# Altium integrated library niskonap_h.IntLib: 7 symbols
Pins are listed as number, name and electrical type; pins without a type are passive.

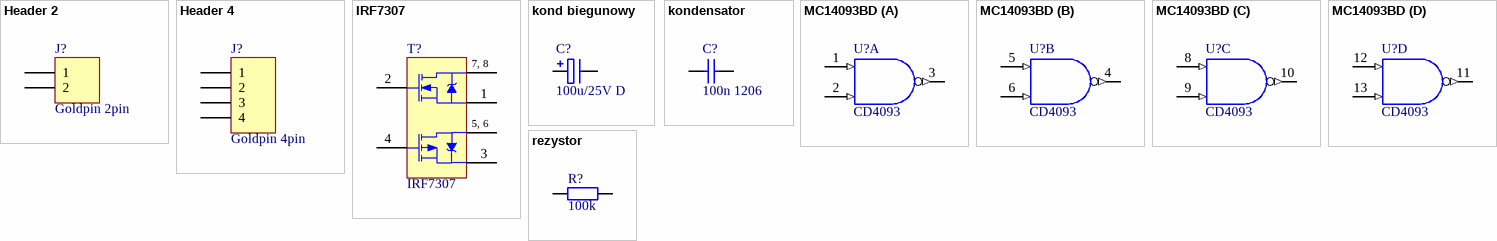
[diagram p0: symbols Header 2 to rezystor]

## Header 2
designator J?, comment Goldpin 2pin
Header, 2-Pin
footprint HDR1X2 (Connector; Header; 2 Position)
signal-integrity model Connector
pins: 1, 2

## Header 4
designator J?, comment Goldpin 4pin
Header, 4-Pin
footprint HDR1X4 (Connector; Header; 4 Position)
signal-integrity model Connector
pins: 1, 2, 3, 4

## IRF7307
designator T?
HEXFET Power MOSFET
footprint SO-8_N (SOIC, 8-Leads, Body 4.9x3.9mm, Pitch 1.27mm, IPC Medium Density)
footprint SO-8_L (SOIC, 8-Leads, Body 4.9x3.9mm, Pitch 1.27mm, IPC High Density)
footprint SO-8_M (SOIC, 8-Leads, Body 4.9x3.9mm, Pitch 1.27mm, IPC Low Density)
3D model SO-8 (8-Pin Plastic Small Outline Integrated Circuit 1.27 mm Pitch)
simulation model IRF7307 (SUBCKT)
pins: 1 S1, 2 G1, 3 S2, 4 G2, 5 D2, 6 D2, 7 D1, 8 D1

## kond biegunowy
designator C?, comment 100u/25V D
Polarized Capacitor
footprint Tantal B 3528-1411 (Capacitor, SM Tantalum; Body 3.5 x 2.8 mm (LxW typ))
footprint Tantal C 6032-2412 (Capacitor, SM Tantalum; Body 6.0 x 3.2 mm (LxW typ))
footprint Tantal D 7343-2917 (Capacitor, SM Tantalum; Body 7.3 x 4.3 mm (LxW typ))
footprint 2,5/5mm elektrolit
footprint 3,5/7mm elektrolit
footprint 5/10mm elektrolit
footprint 2,5/7mm elektrolit
footprint 7,5/16mm elektrolit
footprint 5/12,5mm elektrolit
footprint Tantal A 3216-1206 (Capacitor, SM Tantalum; Body 3.2 x 1.6 mm (LxW typ))
footprint A SMD elektrolit
footprint B SMD elektrolit
footprint C SMD elektrolit
footprint D SMD elektrolit
footprint E SMD elektrolit
footprint F SMD elektrolit
pins: 1, 2
1 alternate drawing of the same symbol

## kondensator
designator C?, comment 100n 1206
footprint kond 2,5mm
footprint kond 7,5mm
footprint kond 10mm
footprint MELF-0805 (Metal Electrode Face (MELF) Resistor; Body 2 x 1.4 mm (LxDia))
footprint MELF-1206 (Metal Electrode Face (MELF) Resistor; Body 3.2 x 1.8 mm (LxDia))
footprint kond 15mm
footprint kond 5mm chudy
footprint kond 5mm gruby
footprint kond 5mm sredni
footprint kond 5mm
pins: 1, 2

## MC14093BD
designator U?, comment CD4093
Quad 2-Input NAND Schmitt Trigger
footprint 751A-03_N (SOIC, 14-Leads, Body 8.7x3.9mm, Pitch 1.27mm, IPC Medium Density)
footprint 751A-03_L (SOIC, 14-Leads, Body 8.7x3.9mm, Pitch 1.27mm, IPC High Density)
footprint 751A-03_M (SOIC, 14-Leads, Body 8.7x3.9mm, Pitch 1.27mm, IPC Low Density)
pins on every part: 7 GND (power) hidden to GND, 14 VDD (power) hidden to VDD
part A pins: 1 A (in), 2 B (in), 3 ~{Y} (out)
part B pins: 4 ~{Y} (out), 5 A (in), 6 B (in)
part C pins: 8 A (in), 9 B (in), 10 ~{Y} (out)
part D pins: 11 ~{Y} (out), 12 A (in), 13 B (in)

## rezystor
designator R?, comment 100k
footprint rez 7,5mm
footprint rez 10mm
footprint rez 12,5mm
footprint rez 15mm
footprint rez 17,5mm
footprint MELF-0805 (Metal Electrode Face (MELF) Resistor; Body 2 x 1.4 mm (LxDia))
footprint MELF-1206 (Metal Electrode Face (MELF) Resistor; Body 3.2 x 1.8 mm (LxDia))
footprint rez_bocznik 20mm
pins: 1, 2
